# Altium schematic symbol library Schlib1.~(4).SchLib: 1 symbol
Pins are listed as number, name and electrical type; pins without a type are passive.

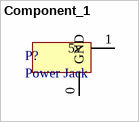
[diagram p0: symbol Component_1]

## Component_1
designator P?, comment Power Jack
pins: 0 GND (power), 1 5v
